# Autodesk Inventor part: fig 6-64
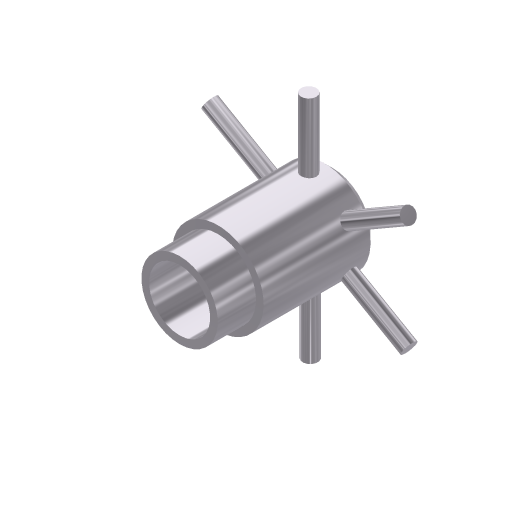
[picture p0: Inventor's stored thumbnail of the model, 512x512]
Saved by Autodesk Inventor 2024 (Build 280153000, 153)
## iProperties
Shininess: 77.0
Angle Display Precision: 2
Document Length Units: 11269
Document Angle Units: 11279
Document Time Units: 11290
Document Mass Units: 11283
Document Length Units Precision: 3
Document Angle Units Precision: 2
Compacted: True
Created: 2001-12
Part Number: fig 6-64
Document SubType Name: Modeling
Designer: Renu Muthoo
Density: 1 g/cm^3
Material: Generic
Appearance: Metal-AL-6061 (Polished)
Density: 0.0
Volumn: 0.0
Area: 0.0
PropertySet Name: Model Information
Control State: 0
Master: False
Checked Out: False
Author: Renu Muthoo
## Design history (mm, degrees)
sketch "Sketch2"
  geometry: L1 (-9.573, -4.327)-(-9.573, -5.327); L2 (-9.573, -5.327)-(-4.573, -5.327); L3 (-4.573, -5.327)-(-4.573, -6.327); L4 (-4.573, -6.327)-(9.427, -6.327); L5 (9.427, -6.327)-(10.427, -5.327); L6 (10.427, -5.327)-(10.427, -4.327); L7 (10.427, -4.327)-(-9.573, -4.327); L8 (-13.687, -0.327)-(14, -0.327)
  constraints: 16 end point, 5 parallel, 1 perpendicular, 1 vertical
  dimensions: "d9" = 20 distance of L6.end L1.start; "d10" = 5 distance of L1.end L2.end; "d11" = 12 diameter of L4 L8; "d12" = 10 diameter of L2 L8; "d13" = 8 diameter of L7 L8; "d14" = 45 deg angle of L5 L4; "d15" = 1 horizontal distance of L5.end L4.end
revolve "Revolution2" sketch "Sketch2" stored, may be unused: angle "d16" = 90 deg
workplane "Work Plane1"
workplane "Work Plane2"
sketch "Sketch3"
  geometry: L1 (-4, 8)-(4, 8) reference; C1 r 1 at (-0.098, 5)
  constraints: 1 centre point
  dimensions: "d18" = 3 distance from line of L1 C1.centre; "d19" = 2 diameter of C1
extrude "Extrusion1" join sketch "Sketch3" distance "d20" = 10; taper "d21" = 0 deg
pattern_circular "Circular Pattern3" dims angle "d29" = 360 deg
body "Solid1"
other parameters: "d17" = -1
